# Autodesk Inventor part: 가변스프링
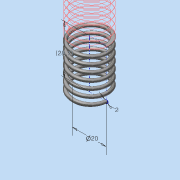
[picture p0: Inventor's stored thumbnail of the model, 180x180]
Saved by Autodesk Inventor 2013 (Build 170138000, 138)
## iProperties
Created: 2020-01
Part Number: 가변스프링
Material: 스테인리스강
Document SubType Name: Modeling
Designer: Administrator
Density: 8.08 g/cm^3
Mass: 10.9959 g
Surface Area: 27.5448 cm^2
Volume: 1.36088 cm^3
Author: Administrator
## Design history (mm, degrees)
sketch "스케치1"
  geometry: L1 (0, 0)-(10, 0); L2 (10, 0)-(10, 28.7); L3 (10, 28.7)-(0, 28.7); L4 (0, 28.7)-(0, 0); C1 r 1 at (10, 0)
  constraints: 8 end point, 2 parallel, 1 centre point, 1 coincident, 1 horizontal, 1 perpendicular
  dimensions: "d0" = 28.7 distance of L3.end L1.start (derived); "d1" = 20 diameter of L2 L4; "d2" = 2 diameter of C1
feature "코일1" sketch "스케치1" pitch "d3" = 10; turns "d5" = 7; dims "d4" = 28.7 (= d0), "d6" = 0, angle "d7" = 90 deg, angle "d8" = 90 deg, "d9" = 0, "d10" = 0
sketch "스케치2"
  geometry: L1 (-9, 0)-(-11, 0) reference; 1 further point
  constraints: 1 horizontal alignment
extrude "돌출1" cut sketch "스케치2" distance "d11" = 10; taper "d12" = 0 deg
node "작업 평면1"
sketch "스케치3"
  geometry: L1 (-1, 0)-(1, 0) reference; 1 further point
  constraints: 1 horizontal alignment
extrude "돌출2" cut sketch "스케치3" distance "d13" = 10; taper "d14" = 0 deg
node "솔리드1"
node "절단 모서리 투영1"
node "절단 모서리 투영2"
